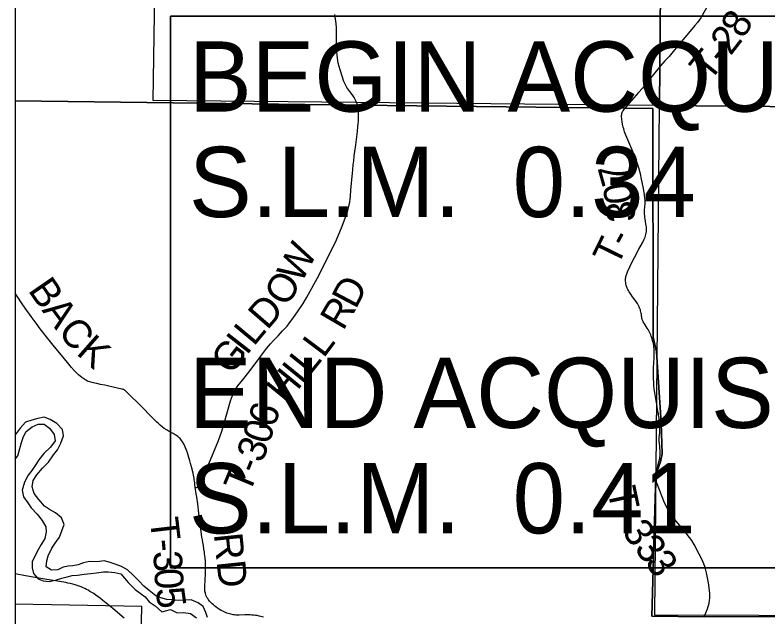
# Model space of a CAD drawing. Extents: x 0 to 34, y 0 to 22.
# Drawn here: x 2.1 to 3.6, y 18.396 to 19.595 of the extents above; entities that cross this region are included whole.
import ezdxf

# ---------------------------------------------------------------- set-up
doc = ezdxf.new("R2010")
doc.units = 0
for name, color, linetype in [('GM_X_Corporation', 7, 'Continuous'), ('GM_X_Major_River', 7, 'Continuous'), ('GM_X_State_Route', 7, 'Continuous'), ('GM_X_Township_Road', 7, 'Continuous'), ('GM_X_Township_Road_Text', 7, 'Continuous'), ('GM_X_Township_Text', 7, 'Continuous'), ('SH_Data', 7, 'Continuous'), ('SH_Text', 7, 'Continuous')]:
    doc.layers.add(name, color=color, linetype=linetype)

msp = doc.modelspace()

# ---------------------------------------------------------------- linework, layer by layer
at = {"layer": 'GM_X_Corporation'}
for points in [[(3.3928, 20.4074), (3.384, 19.4149), (2.3752, 19.4244), (2.3901, 20.4092)], [(3.3928, 20.4074), (4.4129, 20.4084), (4.4084, 19.4053), (3.384, 19.4149)], [(3.384, 19.4149), (4.4084, 19.4053), (4.4097, 18.3961), (3.3747, 18.3998)], [(2.1, 18.4215), (2.1, 17.4478), (2.3314, 17.4451), (2.3525, 18.417)]]:
    msp.add_lwpolyline(points, close=True, dxfattribs=at)
msp.add_lwpolyline([(4.6584, 17.4085), (4.4004, 17.4134), (4.4034, 17.9703), (4.4042, 18.3894), (4.0024, 18.3976), (3.4726, 18.3965), (3.3689, 18.3973), (3.3767, 18.6788), (3.3859, 18.705), (3.3893, 18.721), (3.3872, 18.7823), (3.3779, 18.9241), (3.3711, 18.9531), (3.3709, 19.4088), (3.3147, 19.4093), (2.7824, 19.4152), (2.1, 19.4241), (2.1, 14.1)], dxfattribs=at)
at = {"layer": 'GM_X_Major_River'}
for points in [[(2.465, 18.4238), (2.4509, 18.4301), (2.4388, 18.4296), (2.4255, 18.429), (2.4126, 18.43), (2.4027, 18.4306), (2.3902, 18.4342), (2.3806, 18.4379), (2.3669, 18.4487), (2.3565, 18.4576), (2.3469, 18.4678), (2.3357, 18.4786), (2.3242, 18.4898), (2.312, 18.4965), (2.2994, 18.5012), (2.2872, 18.5053), (2.2777, 18.5078), (2.2637, 18.5057), (2.2482, 18.5066), (2.2364, 18.5038), (2.2255, 18.4995), (2.2153, 18.4978), (2.2058, 18.4973), (2.196, 18.4953), (2.1854, 18.4898), (2.1726, 18.4889), (2.1622, 18.4956), (2.1632, 18.5078), (2.1661, 18.5177), (2.1735, 18.5329), (2.1798, 18.5429), (2.1884, 18.5551), (2.1931, 18.5677), (2.1979, 18.5799), (2.1928, 18.5931), (2.1809, 18.6036), (2.1686, 18.6098), (2.1587, 18.6169), (2.1471, 18.6297), (2.1383, 18.6421), (2.1339, 18.6549), (2.1364, 18.6678), (2.1434, 18.6793), (2.1546, 18.6923), (2.1666, 18.7046), (2.1763, 18.7192), (2.1845, 18.7291), (2.1915, 18.7418), (2.1962, 18.7566), (2.1945, 18.7691), (2.183, 18.7815), (2.17, 18.7893), (2.1578, 18.794), (2.1457, 18.7912), (2.1336, 18.788), (2.1208, 18.7837), (2.1099, 18.7721), (2.1, 18.759)], [(2.1, 18.7103), (2.1054, 18.7171), (2.1097, 18.7312), (2.113, 18.7437), (2.1166, 18.7555), (2.1218, 18.7655), (2.1338, 18.7747), (2.1459, 18.7802), (2.158, 18.78), (2.1687, 18.7718), (2.178, 18.7594), (2.1801, 18.7469), (2.1704, 18.7343), (2.1573, 18.7216), (2.1472, 18.7089), (2.1398, 18.6974), (2.1331, 18.6879), (2.1264, 18.6783), (2.119, 18.6645), (2.1139, 18.6485), (2.1167, 18.6353), (2.1252, 18.6233), (2.1322, 18.6131), (2.1441, 18.6008), (2.1542, 18.5884), (2.1612, 18.5756), (2.1621, 18.5654), (2.1596, 18.5525), (2.1522, 18.5402), (2.1466, 18.5307), (2.1399, 18.5181), (2.134, 18.5058), (2.1342, 18.4937), (2.1366, 18.4827), (2.1459, 18.4722), (2.1558, 18.4678), (2.1679, 18.4665), (2.1827, 18.4701), (2.1929, 18.4733), (2.2035, 18.4761), (2.214, 18.4785), (2.2246, 18.4794), (2.2375, 18.4815), (2.2508, 18.4828), (2.2625, 18.4841), (2.2761, 18.4861), (2.2856, 18.4859), (2.2985, 18.4842), (2.311, 18.4817), (2.3255, 18.4649), (2.3395, 18.4509), (2.3589, 18.4362), (2.3674, 18.4261), (2.3791, 18.4184), (2.3923, 18.4059), (2.4, 18.4083), (2.4098, 18.4106)], [(2.4836, 18.3949), (2.48, 18.4047), (2.475, 18.4168), (2.465, 18.4238)], [(2.4098, 18.4106), (2.4232, 18.4039), (2.4357, 18.4049), (2.4494, 18.4028), (2.4612, 18.3942)]]:
    msp.add_lwpolyline(points, dxfattribs=at)
at = {"layer": 'GM_X_State_Route'}
msp.add_lwpolyline([(2.3175, 18.3939), (2.2945, 18.4128), (2.2748, 18.429), (2.2704, 18.4325), (2.2654, 18.4363), (2.261, 18.4395), (2.2567, 18.4424), (2.2529, 18.4448), (2.2493, 18.447), (2.2457, 18.4491), (2.2422, 18.4509), (2.239, 18.4524), (2.2354, 18.4541), (2.2314, 18.4559), (2.2278, 18.4573), (2.2236, 18.4588), (2.2195, 18.46), (2.2152, 18.4612), (2.2104, 18.4624), (2.2053, 18.4635), (2.2012, 18.4643), (2.1971, 18.4651), (2.1925, 18.4659), (2.1848, 18.4672), (2.1591, 18.4715), (2.1211, 18.4781), (2.1, 18.4817)], dxfattribs=at)
at = {"layer": 'GM_X_Township_Road'}
for points in [[(3.4807, 19.6154), (3.466, 19.5892), (3.4599, 19.5802), (3.4544, 19.5739), (3.4417, 19.5585), (3.4269, 19.5417), (3.4114, 19.5221), (3.4029, 19.5124), (3.3948, 19.5039), (3.3859, 19.4937), (3.3803, 19.4871), (3.3571, 19.4586), (3.3498, 19.4494), (3.342, 19.4403), (3.3232, 19.4193), (3.3149, 19.4088)], [(2.7826, 19.4146), (2.7797, 19.4229), (2.7757, 19.4307), (2.7714, 19.4369), (2.7671, 19.4428), (2.7611, 19.4505), (2.7581, 19.4556), (2.7553, 19.4623), (2.7477, 19.4855), (2.7438, 19.4991), (2.7419, 19.514), (2.7406, 19.5309), (2.7407, 19.553), (2.7407, 19.5696), (2.74, 19.5778), (2.7372, 19.5959)], [(2.459, 18.654), (2.4612, 18.654), (2.4638, 18.655), (2.465, 18.657), (2.4664, 18.6599), (2.4673, 18.662), (2.4687, 18.6654), (2.4858, 18.7009), (2.5054, 18.7477), (2.5115, 18.7641), (2.5162, 18.7792), (2.5293, 18.8266), (2.533, 18.8369), (2.536, 18.8441), (2.5397, 18.8503), (2.5439, 18.8565), (2.5533, 18.8674), (2.5685, 18.8869), (2.5896, 18.9153), (2.6011, 18.9305), (2.609, 18.9401), (2.6151, 18.9466), (2.6239, 18.9559), (2.633, 18.9656), (2.6419, 18.9752), (2.6469, 18.9815), (2.6537, 18.9906), (2.6642, 19.0055), (2.6737, 19.0202), (2.6813, 19.0326), (2.7055, 19.0763), (2.7404, 19.147), (2.7518, 19.1742), (2.7621, 19.203), (2.7665, 19.2194), (2.7668, 19.2227), (2.7675, 19.2281), (2.7681, 19.2339), (2.7691, 19.2462), (2.7704, 19.2597), (2.7712, 19.2664), (2.7718, 19.2738), (2.7721, 19.2787), (2.7728, 19.2879), (2.7735, 19.2959), (2.7743, 19.3014), (2.7746, 19.3039), (2.7759, 19.3143), (2.777, 19.3229), (2.779, 19.3364), (2.7819, 19.363), (2.7831, 19.3729), (2.7837, 19.3787), (2.784, 19.3825), (2.7842, 19.3865), (2.7843, 19.3912), (2.7843, 19.3962), (2.7843, 19.4019), (2.7842, 19.4043), (2.7839, 19.4076), (2.7833, 19.4112), (2.7826, 19.4146)], [(3.3769, 18.6783), (3.3776, 18.6833), (3.3785, 18.6881), (3.3796, 18.6923), (3.3805, 18.6965), (3.3828, 18.7049), (3.3842, 18.7116), (3.3846, 18.7146), (3.385, 18.7177), (3.3852, 18.7205), (3.3854, 18.7233), (3.3853, 18.7276), (3.3848, 18.7319), (3.3845, 18.7351), (3.3837, 18.7425), (3.3835, 18.7449), (3.3834, 18.7478), (3.3834, 18.7499), (3.3834, 18.7518), (3.3835, 18.7539), (3.3837, 18.7579), (3.3842, 18.7628), (3.3843, 18.7646), (3.3844, 18.7665), (3.3845, 18.7686), (3.3845, 18.7708), (3.3845, 18.7729), (3.3845, 18.7746), (3.3843, 18.7775), (3.3843, 18.7787), (3.3841, 18.7818), (3.3838, 18.7854), (3.3835, 18.7878), (3.383, 18.792), (3.3827, 18.7944), (3.3822, 18.7978), (3.3817, 18.8006), (3.3802, 18.8091), (3.3783, 18.8197), (3.377, 18.8265), (3.3756, 18.8343), (3.3743, 18.8422), (3.3732, 18.8508), (3.3727, 18.8565), (3.3724, 18.8607), (3.3718, 18.8725), (3.3717, 18.8824), (3.372, 18.8923), (3.3724, 18.9015), (3.3731, 18.9118), (3.3733, 18.9215), (3.3731, 18.9287), (3.3727, 18.9348), (3.3726, 18.9362), (3.3724, 18.9376), (3.3721, 18.939), (3.3717, 18.9409), (3.3713, 18.9427), (3.3702, 18.9465), (3.3693, 18.9497), (3.3675, 18.955), (3.3663, 18.9582), (3.3652, 18.9607), (3.364, 18.9633), (3.3628, 18.9657), (3.361, 18.9687), (3.3596, 18.971), (3.3551, 18.9777), (3.3539, 18.9795), (3.3524, 18.9818), (3.3513, 18.9837), (3.3504, 18.9859), (3.3495, 18.9883), (3.3489, 18.9905), (3.3486, 18.9919), (3.3484, 18.993), (3.3482, 18.995), (3.3481, 18.9959), (3.3481, 18.9968), (3.348, 18.9978), (3.3478, 18.9994), (3.3475, 19.0006), (3.3462, 19.006), (3.3457, 19.0078), (3.3454, 19.0089), (3.345, 19.0099), (3.3442, 19.012), (3.3435, 19.0137), (3.3414, 19.0179), (3.3398, 19.0206), (3.3387, 19.0223), (3.3372, 19.0244), (3.3347, 19.0279), (3.3302, 19.0339), (3.3266, 19.0389), (3.3234, 19.0437), (3.322, 19.0461), (3.3207, 19.0484), (3.3196, 19.0507), (3.3188, 19.053), (3.318, 19.0551), (3.3175, 19.0571), (3.3169, 19.0594), (3.3166, 19.0614), (3.3161, 19.0657), (3.3161, 19.0672), (3.3162, 19.0687), (3.3163, 19.0704), (3.3166, 19.0719), (3.3171, 19.0742), (3.3182, 19.0777), (3.3203, 19.0834), (3.3245, 19.0931), (3.3288, 19.1021), (3.3339, 19.112), (3.3429, 19.1283), (3.35, 19.1414), (3.3527, 19.147), (3.355, 19.1527), (3.3565, 19.1575), (3.3575, 19.1617), (3.3577, 19.1628), (3.3579, 19.165), (3.3581, 19.1674), (3.3581, 19.1697), (3.3578, 19.1732), (3.3574, 19.1759), (3.3569, 19.1787), (3.3551, 19.1891), (3.3547, 19.1913), (3.3546, 19.1934), (3.3544, 19.1953), (3.3543, 19.1971), (3.3542, 19.2008), (3.3543, 19.2039), (3.3543, 19.2064), (3.355, 19.2194), (3.3551, 19.2232), (3.355, 19.2262), (3.3549, 19.2288), (3.3547, 19.2312), (3.3543, 19.2346), (3.3539, 19.2374), (3.3512, 19.2526), (3.3482, 19.2679), (3.3457, 19.2788), (3.3427, 19.2902), (3.3396, 19.3003), (3.335, 19.3125), (3.329, 19.3275), (3.321, 19.3463), (3.3171, 19.3554), (3.3144, 19.3624), (3.3133, 19.3652), (3.3125, 19.3682), (3.3116, 19.3715), (3.3109, 19.3742), (3.3095, 19.3814), (3.3086, 19.3879), (3.3084, 19.3918), (3.3084, 19.3947), (3.3085, 19.3969), (3.3088, 19.399), (3.3095, 19.4009), (3.3103, 19.4024), (3.3113, 19.4042), (3.3128, 19.4062), (3.3149, 19.4088)], [(2.459, 18.654), (2.4582, 18.6602), (2.4579, 18.6632), (2.4576, 18.6662), (2.4571, 18.6693), (2.4566, 18.6723), (2.4555, 18.6784), (2.4545, 18.6827), (2.4514, 18.6947), (2.4494, 18.7019), (2.4479, 18.7072), (2.4449, 18.7179), (2.4433, 18.7226), (2.4413, 18.7285), (2.4396, 18.7331), (2.4366, 18.7393), (2.4335, 18.7446), (2.4319, 18.7472), (2.4303, 18.7493), (2.4287, 18.7512), (2.427, 18.753), (2.4243, 18.7552), (2.4217, 18.7571), (2.4189, 18.7589), (2.4147, 18.7613), (2.4093, 18.7642), (2.4029, 18.7679), (2.3971, 18.7716), (2.3936, 18.7742), (2.3889, 18.7781), (2.3856, 18.7811), (2.3823, 18.7842), (2.3731, 18.793), (2.3683, 18.7978), (2.3549, 18.8116), (2.3457, 18.8208), (2.3303, 18.8362), (2.3209, 18.8456), (2.32, 18.8465), (2.319, 18.8474), (2.3181, 18.848), (2.3172, 18.8484), (2.3164, 18.8487), (2.3155, 18.849), (2.3146, 18.8492), (2.3136, 18.8495), (2.3066, 18.8511), (2.2952, 18.8539), (2.2867, 18.8558), (2.2788, 18.8574), (2.2702, 18.8592), (2.263, 18.8607), (2.2587, 18.8617), (2.2539, 18.8629), (2.2491, 18.8643), (2.2445, 18.8659), (2.2411, 18.8675), (2.2368, 18.87), (2.2328, 18.8729), (2.2266, 18.8781), (2.2218, 18.883), (2.218, 18.8871), (2.2127, 18.8931), (2.2046, 18.9026), (2.1951, 18.914), (2.1756, 18.9374), (2.1624, 18.9538), (2.1503, 18.9696), (2.1418, 18.981), (2.1324, 18.9942), (2.1201, 19.0113), (2.1144, 19.0194), (2.1104, 19.0255), (2.1084, 19.0286), (2.1049, 19.0337), (2.1024, 19.0373), (2.1, 19.0411)], [(3.4728, 18.3959), (3.4792, 18.4119), (3.4825, 18.4233), (3.4842, 18.4343), (3.4842, 18.4433), (3.4814, 18.4637), (3.4776, 18.4839), (3.4749, 18.4943), (3.4723, 18.5017), (3.4682, 18.5112), (3.4632, 18.5211), (3.453, 18.5401), (3.4481, 18.5481), (3.4438, 18.5545), (3.4371, 18.5628), (3.4208, 18.5818), (3.4137, 18.5908), (3.4021, 18.6078), (3.3937, 18.6231), (3.3877, 18.6387), (3.3841, 18.649), (3.3782, 18.6646), (3.3769, 18.6783)], [(2.5951, 18.3958), (2.5926, 18.3965), (2.5897, 18.3972), (2.5865, 18.3978), (2.5824, 18.3986), (2.5792, 18.3991), (2.5755, 18.3995), (2.5718, 18.3998), (2.5684, 18.4), (2.5643, 18.4002), (2.5575, 18.4), (2.5463, 18.3996), (2.5432, 18.3996), (2.5401, 18.3998), (2.5375, 18.4001), (2.5346, 18.4004), (2.5322, 18.4008), (2.5297, 18.4014), (2.5271, 18.402), (2.5243, 18.4029), (2.5218, 18.4038), (2.5191, 18.4049), (2.5165, 18.406), (2.514, 18.4073), (2.5108, 18.409), (2.5072, 18.4111), (2.5034, 18.4135), (2.5001, 18.416), (2.4978, 18.4177), (2.4953, 18.4198), (2.4926, 18.4223), (2.4907, 18.424), (2.4887, 18.4261), (2.4872, 18.4277), (2.486, 18.4291), (2.4849, 18.4306), (2.4838, 18.4325), (2.4828, 18.434), (2.4819, 18.4357), (2.4809, 18.4379), (2.4802, 18.4397), (2.4792, 18.4433), (2.4786, 18.4453), (2.4783, 18.4475), (2.478, 18.4494), (2.4779, 18.4511), (2.4778, 18.4527), (2.4778, 18.4551), (2.4779, 18.4574), (2.4785, 18.4691), (2.4792, 18.4827), (2.4794, 18.4882), (2.4795, 18.4919), (2.4796, 18.4976), (2.4793, 18.5066), (2.4787, 18.5137), (2.4777, 18.5215), (2.4772, 18.5252), (2.4763, 18.5313), (2.4751, 18.538), (2.4741, 18.5441), (2.4731, 18.5496), (2.4723, 18.5551), (2.4714, 18.5612), (2.4689, 18.5805), (2.4664, 18.603), (2.4641, 18.6213), (2.4619, 18.6346), (2.4609, 18.6413), (2.4601, 18.6456), (2.459, 18.654)]]:
    msp.add_lwpolyline(points, dxfattribs=at)
at = {"layer": 'GM_X_Township_Text'}
for points in [[(6.4525, 17.3965), (6.4653, 18.1777), (6.4655, 18.1862), (6.4767, 18.8745), (6.4767, 18.8755), (6.4827, 20.9), (2.1, 20.9), (2.1, 19.4241)], [(2.1, 19.4241), (2.7824, 19.4152), (3.3147, 19.4093), (3.3709, 19.4088), (3.3711, 18.9531), (3.3779, 18.9241), (3.3872, 18.7823), (3.3893, 18.721), (3.3859, 18.705), (3.3767, 18.6788), (3.3689, 18.3973), (3.4726, 18.3965), (4.0024, 18.3976), (4.4042, 18.3894), (4.4034, 17.9703), (4.4004, 17.4134), (4.6584, 17.4085)], [(2.1, 19.4241), (2.1, 16.074), (2.3294, 16.0685), (2.5414, 16.0663), (3.0911, 16.0497), (3.9428, 16.0275), (4.0565, 16.0246), (4.383, 16.0223), (4.3994, 17.3911), (4.4004, 17.4134)]]:
    msp.add_lwpolyline(points, dxfattribs=at)
at = {"layer": 'SH_Data'}
msp.add_line((2.1, 20.9), (2.1, 14.1), dxfattribs=at)
at = {"layer": 'SH_Text'}
for points in [[(4.4854, 19.5924), (2.4095, 19.5924), (2.4095, 18.4935), (4.4854, 18.4935)], [(2.4095, 19.5924), (4.4854, 19.5924), (4.4854, 18.4935), (2.4095, 18.4935)]]:
    msp.add_lwpolyline(points, close=True, dxfattribs=at)

# ---------------------------------------------------------------- texts
at = {"layer": 'GM_X_Township_Road_Text'}
for s, height, rotation, p in [('8', 0.0568, 58.84, (3.5508, 19.5459)), ('2', 0.0568, 52.3664, (3.5255, 19.5124)), ('T', 0.0568, 51.124, (3.4834, 19.4601)), ('-', 0.0568, 51.3386, (3.5102, 19.4934)), ('7', 0.0568, 105.6764, (3.3261, 19.2648)), ('0', 0.0568, 98.5311, (3.3329, 19.2229)), ('3', 0.0568, 95.3688, (3.3366, 19.1849)), ('T', 0.0568, 63.9676, (3.2998, 19.0916)), ('-', 0.0568, 61.3303, (3.3181, 19.1291)), ('W', 0.0568, 62.4239, (2.6697, 19.0581)), ('O', 0.0568, 58.1517, (2.641, 19.0116)), ('B', 0.0568, 304.5377, (2.1247, 19.0467)), ('D', 0.0568, 62.2872, (2.7786, 19.0072)), ('A', 0.0568, 306.3158, (2.1522, 19.0067)), ('D', 0.0568, 49.1043, (2.6025, 18.9659)), ('R', 0.0568, 59.6788, (2.7537, 18.9644)), ('C', 0.0568, 308.7513, (2.1835, 18.9643)), ('L', 0.0568, 50.2136, (2.5755, 18.9335)), ('I', 0.0568, 52.0216, (2.5614, 18.9155)), ('K', 0.0568, 318.6656, (2.2201, 18.9202)), ('G', 0.0568, 52.2209, (2.5308, 18.876)), ('L', 0.0568, 53.0507, (2.7146, 18.91)), ('L', 0.0568, 51.1093, (2.6866, 18.8753)), ('I', 0.0568, 50.8636, (2.6717, 18.857)), ('H', 0.0568, 50.8003, (2.6401, 18.8182)), ('6', 0.0568, 71.2014, (2.6162, 18.7709)), ('0', 0.0568, 73.1596, (2.6062, 18.7379)), ('3', 0.0568, 68.8954, (2.5921, 18.7009)), ('-', 0.0568, 67.7199, (2.5828, 18.6781)), ('T', 0.0568, 67.4035, (2.5663, 18.6385)), ('T', 0.0568, 281.9706, (3.2796, 18.6496)), ('-', 0.0568, 299.8915, (3.2953, 18.59)), ('T', 0.0568, 276.7051, (2.3682, 18.5912)), ('3', 0.0568, 301.8826, (3.308, 18.5679)), ('RD', 0.05682, 275.9567, (2.4958, 18.5609)), ('3', 0.0568, 310.2199, (3.3318, 18.5309)), ('-', 0.0568, 275.01, (2.3731, 18.5494)), ('3', 0.0568, 273.5306, (2.3751, 18.5265)), ('3', 0.0568, 303.6814, (3.3534, 18.5055)), ('0', 0.0568, 273.3167, (2.3773, 18.4917)), ('5', 0.0568, 277.7716, (2.3798, 18.4519))]:
    msp.add_text(s, height=height, rotation=rotation, dxfattribs=at).set_placement(p)
at = {"layer": 'SH_Text'}
for s, p in [('BEGIN ACQUISITION', (2.4465, 19.4024)), ('S.L.M.  0.34', (2.4465, 19.1924)), ('END ACQUISITION', (2.4465, 18.7724)), ('S.L.M.  0.41', (2.4465, 18.5624))]:
    msp.add_text(s, height=0.14, dxfattribs=at).set_placement(p)

doc.saveas('drawing.dxf')
